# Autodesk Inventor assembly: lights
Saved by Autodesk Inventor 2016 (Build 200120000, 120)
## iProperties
Created: 2018-05
Part Number: lights
Document SubType Name: Assembly
Designer: Administrator
Title: lights
Author: Administrator
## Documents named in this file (3)
- c:\worker\convert-fusion-mar-2018\tmp\job-1\16\output\files\8c58ff39-88bb-4352-afd9-60265520bae5\lights.iam
- c:\worker\convert-fusion-mar-2018\tmp\job-1\16\output\files\8c58ff39-88bb-4352-afd9-60265520bae5\led_org.ipt
- c:\worker\convert-fusion-mar-2018\tmp\job-1\16\output\files\8c58ff39-88bb-4352-afd9-60265520bae5\lights.ipt
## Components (3 placed, 2 different names)
1. led_org:1
2. led_org:2
3. lights
